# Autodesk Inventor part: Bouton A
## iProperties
Created: 2010-07
Part Number: Bouton A
Document SubType Name: Modeling
Designer: eric
Density: 1 g/cm^3
Mass: 0.32175 g
Surface Area: 3.53124 cm^2
Volume: 0.32175 cm^3
Author: eric
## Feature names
1. Extrusion1
2. Revolution1
3. Extrusion2
